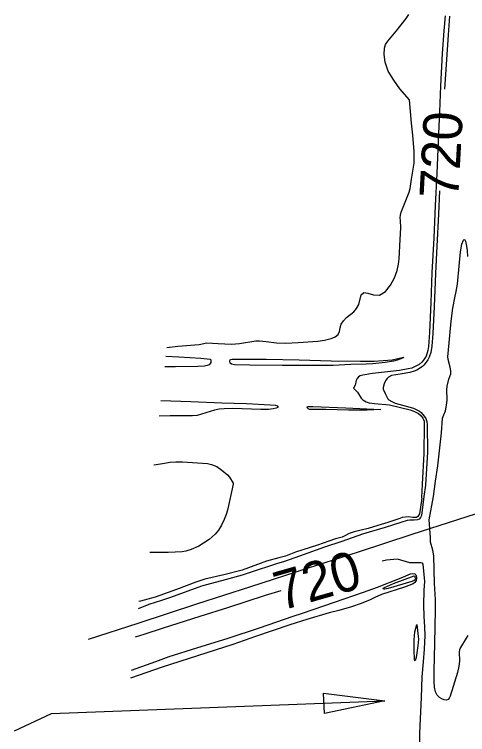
# Model space of a CAD drawing. Extents: x -310467766 to 17062430, y -322263100 to 8322522.
# Drawn here: x 1395365 to 1395749, y 573612 to 574223 of the extents above; entities that cross this region are included whole.
import ezdxf

# ---------------------------------------------------------------- set-up
doc = ezdxf.new("R2010")
doc.units = 0
for name, color, linetype in [('DT_X_Contour_Minor', 7, 'Continuous'), ('Level 14', 7, 'Continuous'), ('Level 19', 7, 'Continuous'), ('Level 40', 7, 'Continuous')]:
    doc.layers.add(name, color=color, linetype=linetype)

msp = doc.modelspace()

# ---------------------------------------------------------------- linework, layer by layer
at = {"layer": 'DT_X_Contour_Minor'}
for points in [[(1395730.09, 574221.35), (1395729.18, 574208.72), (1395727.77, 574189.52), (1395726.32, 574161.95), (1395725.46, 574140.11), (1395724.41, 574115.51), (1395723.25, 574087.69), (1395721.85, 574060.39), (1395720.57, 574032.71), (1395719.03, 574003.68), (1395717.97, 573978.31), (1395716.94, 573952.82), (1395716.11, 573940.78), (1395715.57, 573937.59), (1395714.05, 573932.77), (1395712.44, 573930.04), (1395710.69, 573927.83), (1395708.11, 573925.71), (1395705.42, 573924.07), (1395701.85, 573922.58), (1395698.72, 573921.84), (1395691.56, 573920.61), (1395668.52, 573917.95), (1395660.41, 573916.68), (1395658.2, 573915.91), (1395656.73, 573915.13), (1395655.47, 573913.85), (1395654.71, 573912.01), (1395653.79, 573908.14), (1395652.58, 573905.4), (1395654.46, 573903.52), (1395655.72, 573902.17), (1395658.88, 573897.09), (1395660.34, 573895.74), (1395663.33, 573893.99), (1395665.62, 573893.21), (1395670.4, 573892.64), (1395683.13, 573891.39), (1395700.64, 573887.14), (1395704.15, 573885.88), (1395707.59, 573883.96), (1395709.82, 573881.94), (1395711.14, 573880.08), (1395712.41, 573877.44), (1395712.54, 573874.32), (1395712.18, 573850.12), (1395710.7, 573824.04), (1395710.23, 573812.74), (1395710.46, 573812.22), (1395708.48, 573798.85), (1395707.16, 573796.8), (1395705.78, 573795.95), (1395704.62, 573795.73), (1395702.73, 573795.71), (1395699.14, 573796.26), (1395693.84, 573795.78), (1395690.9, 573794.8), (1395681.61, 573791.59), (1395673.07, 573789.04), (1395664.89, 573786.5), (1395653.14, 573783.74), (1395648.69, 573782.19), (1395644.98, 573780.29), (1395642.79, 573779.25), (1395637.2, 573777.66), (1395631.56, 573775.82), (1395621.8, 573772.4), (1395603.24, 573766.3), (1395594.84, 573763.11), (1395589.01, 573761.64), (1395578.57, 573758.89), (1395558.01, 573751.23), (1395542.5, 573747.21), (1395526.24, 573743.46), (1395518.82, 573740.91), (1395502.37, 573734.83), (1395488.16, 573729.56), (1395484.18, 573728.28), (1395471.84, 573724.96), (1395470.43, 573724.55)], [(1395494.09, 573940), (1395503.53, 573941.12), (1395521.39, 573942.63), (1395528.07, 573943.99), (1395537.77, 573943.37), (1395549.01, 573942.73), (1395555.83, 573943.4), (1395569.51, 573945.66), (1395572.72, 573945.79), (1395578.38, 573945.07), (1395587.04, 573944.13), (1395595.01, 573943.75), (1395605.4, 573944.17), (1395622.3, 573945.41), (1395627.74, 573946.13), (1395633.55, 573947.66), (1395636.89, 573949.07), (1395639.43, 573951.05), (1395640.6, 573953.67), (1395641.09, 573956.67), (1395641.92, 573959.76), (1395643.85, 573962.66), (1395646.61, 573965.37), (1395652.63, 573970.41), (1395655.12, 573973.18), (1395656.94, 573976.63), (1395659.1, 573984.71), (1395661.1, 573986.75), (1395664.69, 573986.14), (1395669.42, 573984.61), (1395674.59, 573984.5), (1395679.55, 573987.54), (1395683.9, 573992.93), (1395687.29, 573999.26), (1395689.47, 574005.3), (1395690.67, 574010.7), (1395691.2, 574015.31), (1395692.03, 574031.6), (1395692.75, 574041.5), (1395692.27, 574047.78), (1395692.05, 574050.06), (1395692.21, 574052.35), (1395692.84, 574054.95), (1395695.64, 574061.96), (1395699.82, 574071.85), (1395700.43, 574074.88), (1395701.78, 574082.91), (1395703.85, 574096.3), (1395704.05, 574101.25), (1395703.85, 574106.2), (1395702.77, 574120.18), (1395701.62, 574130.37), (1395699.88, 574150.21), (1395691.89, 574159.63), (1395686.55, 574166.73), (1395681.97, 574174.53), (1395679.36, 574182.1), (1395678.48, 574188.75), (1395678.74, 574193.88), (1395679.7, 574197.22), (1395681.51, 574199.87), (1395688.73, 574208.32), (1395697.06, 574219.11), (1395699.37, 574222.63)], [(1395733.89, 574221.19), (1395732.69, 574205.34), (1395729.52, 574159.17)], [(1395725.41, 574072.99), (1395724.46, 574053.22), (1395723.06, 574026.13), (1395722.02, 574002.76), (1395720.75, 573974.87), (1395719.74, 573951.82), (1395718.96, 573941.1), (1395717.94, 573935.68), (1395716.62, 573931.76), (1395715.51, 573929.58), (1395712.48, 573925.37), (1395711.04, 573923.97), (1395706.24, 573920.93), (1395703.85, 573919.83), (1395700.12, 573918.81), (1395691.94, 573917.46), (1395684.76, 573916.22), (1395682.07, 573914.76), (1395680.91, 573913.73), (1395679.92, 573912.33), (1395678.41, 573909.11), (1395677.6, 573906.17), (1395677.75, 573904.59), (1395679.34, 573900.9), (1395681.69, 573896.6), (1395682.55, 573895.65), (1395685.04, 573894.12), (1395687.9, 573892.86), (1395703.35, 573888.5), (1395708.32, 573886.02), (1395709.72, 573884.85), (1395712.53, 573881.89), (1395713.68, 573879.84), (1395714.77, 573877.36), (1395715.07, 573874.54), (1395715.1, 573851.29), (1395713.47, 573823.3), (1395712.24, 573813.7), (1395710.07, 573797.54), (1395709.27, 573795.71), (1395708.16, 573794.47), (1395706.81, 573793.9), (1395704.02, 573793.65), (1395700.25, 573793.48), (1395697.88, 573793.13), (1395692.55, 573791.58), (1395679.19, 573787.2), (1395665.63, 573783.29), (1395660.1, 573781.81), (1395642.49, 573775.34), (1395627.87, 573770.59), (1395606.73, 573763.08), (1395593.13, 573758.24), (1395587.97, 573756.77), (1395564.01, 573748.86), (1395558.05, 573746.83), (1395543.57, 573742.9), (1395523.55, 573737.55), (1395497.2, 573728.05), (1395489.65, 573725.33), (1395478.88, 573721.88), (1395469.76, 573718.38)], [(1395749.37, 573695.74), (1395748.14, 573693.33), (1395743.17, 573685.54), (1395742.34, 573683.61), (1395742.08, 573681.89), (1395742.33, 573674.05), (1395741.8, 573669.7), (1395740.56, 573664.37), (1395734.47, 573644.13), (1395733.75, 573642.47), (1395732.71, 573641.33), (1395731.23, 573640.93), (1395729.41, 573641.19), (1395727.38, 573641.95), (1395725.32, 573643.16), (1395723.44, 573645.04), (1395722, 573647.9), (1395721.16, 573651.9), (1395720.81, 573656.59), (1395720.85, 573665.85), (1395721.55, 573689.05), (1395722.1, 573717.37), (1395722.04, 573726.17), (1395721.15, 573739.69), (1395720.56, 573763.24), (1395719.69, 573768.1), (1395717.67, 573775.01), (1395717.8, 573778.73), (1395716.51, 573793.74), (1395720.42, 573813.5), (1395722.03, 573826.75), (1395723.96, 573839.7), (1395725.36, 573852.33), (1395727.2, 573867.52), (1395728.08, 573879.99), (1395728.99, 573882.83), (1395730.38, 573886.44), (1395731.62, 573892.68), (1395731.88, 573895.95), (1395731.54, 573904.12), (1395731.91, 573907.15), (1395733.46, 573913.1), (1395734.89, 573917.61), (1395735, 573920.14), (1395734.47, 573923.32), (1395732.87, 573929.82), (1395732.55, 573932.28), (1395732.64, 573935.09), (1395735.33, 573962.5), (1395736.7, 573973.5), (1395738.48, 573982.28), (1395739.55, 573987.42), (1395740.55, 573993.64), (1395742, 574008.95), (1395743.18, 574021.22), (1395744.44, 574027.63), (1395745.75, 574030.98), (1395746.35, 574031.55), (1395746.89, 574031.26), (1395747.4, 574030.19), (1395748.43, 574025.89), (1395748.91, 574022.29), (1395749.28, 574017.14)], [(1395493.28, 573932.69), (1395504.27, 573932.03), (1395523.04, 573931.02), (1395530.76, 573930.02), (1395531.48, 573929.44), (1395531.54, 573928.93), (1395531.34, 573927.45), (1395530.91, 573926.41), (1395529.97, 573925.46), (1395528.38, 573924.76), (1395526.16, 573924.33), (1395520.27, 573924.01), (1395501.51, 573923.71), (1395492.28, 573923.52)], [(1395625.26, 573924.69), (1395607.73, 573924.74), (1395591.81, 573924.65), (1395564.43, 573925.02), (1395551.39, 573925.46), (1395548.89, 573925.91), (1395547.92, 573926.71), (1395547.64, 573928.35), (1395547.88, 573929.56), (1395548.37, 573929.96), (1395549.6, 573930.18), (1395554.12, 573930.28), (1395578.43, 573930.09), (1395606.29, 573929.51), (1395633.49, 573928.83), (1395658.42, 573928.47), (1395670.04, 573928.44), (1395685.39, 573929.46), (1395694.96, 573931.9), (1395694.72, 573931.39), (1395694.16, 573930.94), (1395689.44, 573929.24), (1395686.46, 573928.34), (1395679.46, 573927.35), (1395668.85, 573926.08), (1395663.2, 573925.86), (1395650.12, 573925.53), (1395635.31, 573924.71), (1395625.26, 573924.69)], [(1395489.15, 573894.99), (1395514.32, 573894.12), (1395540.77, 573893.15), (1395561.63, 573892.45), (1395581.71, 573891.51), (1395586.41, 573890.99), (1395587.79, 573890.43), (1395588.23, 573889.79), (1395588.13, 573889.24), (1395586.99, 573888.69), (1395584.26, 573887.96), (1395580.39, 573887.45), (1395573.85, 573887.5), (1395550, 573888.41), (1395542.79, 573888.07), (1395538.62, 573887.6), (1395534.51, 573886.78), (1395519.9, 573882.29), (1395515.9, 573881.94), (1395506.71, 573881.96), (1395496.81, 573882.12), (1395487.7, 573881.8)], [(1395675.57, 573887.38), (1395664.01, 573886.94), (1395648.12, 573886.98), (1395628.93, 573887.39), (1395615.06, 573887.55), (1395613.86, 573887.95), (1395613.33, 573888.48), (1395613.24, 573889.41), (1395613.56, 573889.9), (1395614.24, 573890.09), (1395617.86, 573890.04), (1395646.01, 573888.8), (1395675.57, 573887.38)], [(1395483.16, 573840.45), (1395488.65, 573841.26), (1395496.87, 573842.64), (1395501.7, 573843), (1395507.28, 573842.95), (1395528.68, 573841.68), (1395531.95, 573840.85), (1395536.57, 573838.99), (1395540.87, 573835.9), (1395545.47, 573832.06), (1395547.25, 573829.98), (1395550.42, 573825.04), (1395550.33, 573824.17), (1395545.59, 573802.05), (1395544.42, 573798.36), (1395542.71, 573793.99), (1395540.49, 573789.35), (1395537.87, 573785.04), (1395535, 573781.57), (1395529.98, 573777.17), (1395525.34, 573773.96), (1395521.33, 573771.63), (1395514.77, 573768.79), (1395510.21, 573767.24), (1395507.01, 573766.8), (1395495.2, 573766.17), (1395479.72, 573766.24)], [(1395708.16, 573582.97), (1395708.85, 573612.77), (1395710.03, 573643.18), (1395710.77, 573660.6), (1395711.93, 573673.26), (1395712.81, 573684.04), (1395713.3, 573695.76), (1395713.05, 573702.71), (1395712.34, 573712.06), (1395712.15, 573721.3), (1395712.41, 573734.11), (1395712.85, 573741.49), (1395712.48, 573747.32), (1395711.5, 573756.19), (1395710.88, 573757.1), (1395709.57, 573757.4), (1395704.8, 573757.34), (1395700.26, 573757.29), (1395689.85, 573760.48), (1395680.48, 573759.64), (1395676.87, 573758.79)], [(1395464.05, 573666.38), (1395484.67, 573673.51), (1395496.19, 573677.77), (1395519.69, 573685.34), (1395546.24, 573693.52), (1395572.74, 573702.27), (1395601.32, 573712.19), (1395609.28, 573714.69), (1395636.31, 573724.09), (1395660.88, 573732.48), (1395672.81, 573736.7), (1395692.91, 573744.75), (1395700.94, 573748.15), (1395702.89, 573748.44), (1395704.35, 573748.15), (1395705.23, 573747.27), (1395705.92, 573745.19), (1395705.96, 573743.96), (1395705.59, 573742.29), (1395704.6, 573740.63), (1395703.01, 573739.43), (1395695.68, 573736.58), (1395676.08, 573730.35), (1395670.68, 573728.03), (1395666.5, 573725.9), (1395658.89, 573722.73), (1395650.72, 573720.07), (1395640.1, 573717.05), (1395631.87, 573714.93), (1395612.76, 573709.29), (1395598.55, 573704.74), (1395569.39, 573694.73), (1395549.98, 573688), (1395520.08, 573678.59), (1395490.16, 573668.77), (1395463.29, 573659.49)], [(1395701.84, 573741.57), (1395681.92, 573735.69), (1395679.03, 573735.11), (1395677.88, 573735.14), (1395677.61, 573735.44), (1395677.66, 573735.77), (1395678.63, 573736.38), (1395686.45, 573739.7), (1395703.8, 573746.44), (1395704.28, 573746.1), (1395704.94, 573743.87), (1395704.72, 573743.04), (1395704.06, 573742.43), (1395701.84, 573741.57)], [(1395590.78, 573733.47), (1395577.53, 573729.5), (1395545.59, 573719.12), (1395522.19, 573711.8), (1395491.09, 573701.91), (1395474.51, 573696.57), (1395467.12, 573694.34)], [(1395706.08, 573704.97), (1395707.45, 573694.83), (1395707.59, 573692.66), (1395707.08, 573687), (1395705.55, 573677.01), (1395704.8, 573674.23), (1395704.27, 573675.2), (1395703.79, 573683.63), (1395703.8, 573692), (1395704.59, 573698.79), (1395706.08, 573704.97)]]:
    msp.add_lwpolyline(points, dxfattribs=at)
at = {"layer": 'Level 14'}
msp.add_lwpolyline([(1396045.69, 573892.73), (1396001.03, 573878.02), (1395955.53, 573863.35), (1395911.76, 573849.15), (1395869, 573835.4), (1395822.72, 573820.18), (1395779.38, 573806.32), (1395701.9, 573781.33), (1395656.33, 573766.51), (1395613.86, 573752.89), (1395565.14, 573737), (1395519.21, 573722.15), (1395469.52, 573705.79), (1395427.26, 573692.2)], dxfattribs=at)
at = {"layer": 'Level 40'}
for p, q in [((1395627.13, 573646.83), (1395678.99, 573640.15)), ((1395627.77, 573629.66), (1395627.13, 573646.83)), ((1395396.34, 573629.62), (1395678.99, 573640.15)), ((1395678.99, 573640.15), (1395627.77, 573629.66)), ((1395364.79, 573614.91), (1395396.34, 573629.62))]:
    msp.add_line(p, q, dxfattribs=at)

# ---------------------------------------------------------------- texts
at = {"layer": 'Level 19'}
for rotation, p in [(86.89478, (1395741.25, 574065.83)), (15.99125, (1395590.69, 573716.53))]:
    msp.add_text('720', height=33, rotation=rotation, dxfattribs=at).set_placement(p)

doc.saveas('drawing.dxf')
